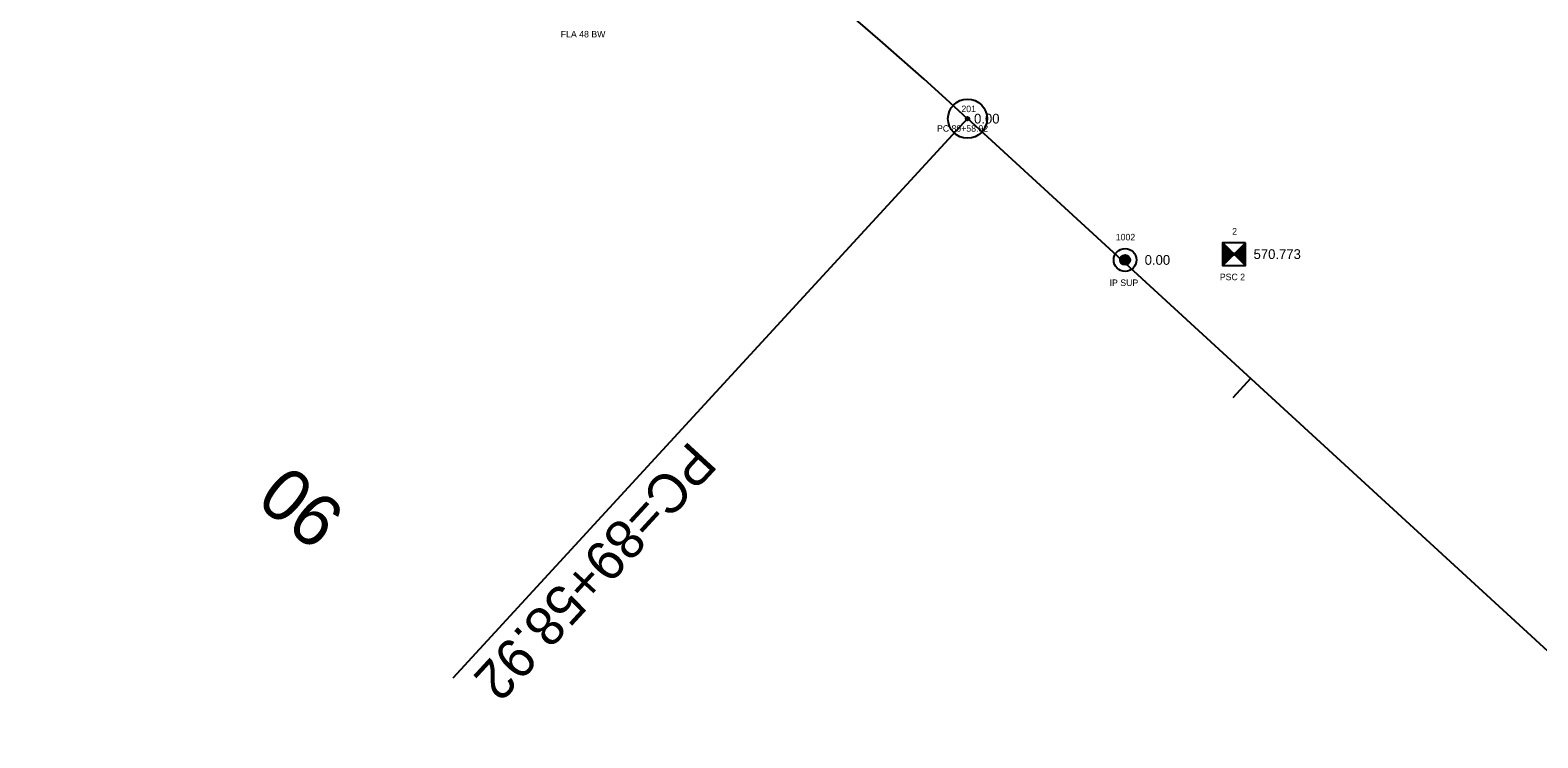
# Model space of a CAD drawing. Extents: x 1529475 to 1532053, y 876698 to 877911.
# Drawn here: x 1531499.1 to 1531730.2, y 876997.3 to 877105.9 of the extents above; entities that cross this region are included whole.
import ezdxf

# ---------------------------------------------------------------- set-up
doc = ezdxf.new("R2010")
doc.units = 0
for name, color, linetype in [('RD_EX_DV_Prop_txCode', 7, 'Continuous'), ('RD_EX_DV_PropPin', 7, 'Continuous'), ('RD_EX_Fence_Other_txCode', 7, 'Continuous'), ('RD_EX_TX_DV_Prop_ELEV', 7, 'Continuous'), ('RD_HC_Cl', 7, 'Continuous'), ('RD_HC_Data', 7, 'Continuous'), ('RD_HC_Data_Tic', 7, 'Continuous'), ('RD_HC_Survey', 7, 'Continuous'), ('RD_HC_Survey_ELEV', 7, 'Continuous'), ('RD_HC_TX_Sta50', 7, 'Continuous'), ('RD_HC_txCode', 7, 'Continuous'), ('RD_SMD_Locator', 7, 'Continuous')]:
    doc.layers.add(name, color=color, linetype=linetype)

msp = doc.modelspace()

# ---------------------------------------------------------------- linework, layer by layer
at = {"layer": 'RD_EX_DV_PropPin'}
for p, q in [((1531666.3, 877070.22), (1531666.3, 877071.07)), ((1531666.33, 877070.17), (1531666.33, 877071.12)), ((1531666.37, 877070.13), (1531666.37, 877071.16)), ((1531666.4, 877070.1), (1531666.4, 877071.2)), ((1531666.44, 877070.06), (1531666.44, 877071.23)), ((1531666.47, 877070.04), (1531666.47, 877071.26)), ((1531666.51, 877070.01), (1531666.51, 877071.28)), ((1531666.54, 877069.99), (1531666.54, 877071.3)), ((1531666.58, 877069.97), (1531666.58, 877071.32)), ((1531666.61, 877069.95), (1531666.61, 877071.34)), ((1531666.65, 877069.94), (1531666.65, 877071.35)), ((1531666.68, 877069.93), (1531666.68, 877071.37)), ((1531666.72, 877069.91), (1531666.72, 877071.38)), ((1531666.75, 877069.91), (1531666.75, 877071.39)), ((1531666.79, 877069.9), (1531666.79, 877071.39)), ((1531666.82, 877069.89), (1531666.82, 877071.4)), ((1531666.86, 877069.89), (1531666.86, 877071.4)), ((1531666.89, 877069.89), (1531666.89, 877071.41)), ((1531666.93, 877069.89), (1531666.93, 877071.41)), ((1531666.96, 877069.89), (1531666.96, 877071.41)), ((1531667, 877069.89), (1531667, 877071.4)), ((1531667.03, 877069.89), (1531667.03, 877071.4)), ((1531667.07, 877069.9), (1531667.07, 877071.39)), ((1531667.1, 877069.91), (1531667.1, 877071.39)), ((1531667.14, 877069.91), (1531667.14, 877071.38)), ((1531667.17, 877069.93), (1531667.17, 877071.37)), ((1531667.21, 877069.94), (1531667.21, 877071.35)), ((1531667.24, 877069.95), (1531667.24, 877071.34)), ((1531667.28, 877069.97), (1531667.28, 877071.32)), ((1531667.31, 877069.99), (1531667.31, 877071.3)), ((1531667.35, 877070.01), (1531667.35, 877071.28)), ((1531667.38, 877070.04), (1531667.38, 877071.26)), ((1531667.42, 877070.06), (1531667.42, 877071.23)), ((1531667.45, 877070.1), (1531667.45, 877071.2)), ((1531667.49, 877070.13), (1531667.49, 877071.16)), ((1531667.52, 877070.17), (1531667.52, 877071.12)), ((1531667.56, 877070.22), (1531667.56, 877071.07)), ((1531666.19, 877070.45), (1531666.19, 877070.84)), ((1531666.23, 877070.35), (1531666.23, 877070.94)), ((1531666.26, 877070.28), (1531666.26, 877071.02)), ((1531667.59, 877070.28), (1531667.59, 877071.02)), ((1531667.63, 877070.35), (1531667.63, 877070.94)), ((1531667.66, 877070.45), (1531667.66, 877070.84))]:
    msp.add_line(p, q, dxfattribs=at)
for radius in [1.75, 0.761]:
    msp.add_circle((1531666.93, 877070.65), radius, dxfattribs=at)
at = {"layer": 'RD_HC_Cl'}
msp.add_line((1531961.27, 876799.7), (1531642.78, 877092.32), dxfattribs=at)
msp.add_arc((1531152.26, 876558.44), 725, 47.4237, 92.33207, dxfattribs=at)
at = {"layer": 'RD_HC_Data'}
msp.add_line((1531642.78, 877092.32), (1531563.91, 877006.48), dxfattribs=at)
for radius in [3, 0.282]:
    msp.add_circle((1531642.78, 877092.32), radius, dxfattribs=at)
at = {"layer": 'RD_HC_Data_Tic'}
msp.add_line((1531686.17, 877052.45), (1531683.46, 877049.51), dxfattribs=at)
at = {"layer": 'RD_HC_Survey'}
for p, q in [((1531681.87, 877073.28), (1531685.37, 877069.79)), ((1531685.37, 877073.28), (1531681.87, 877069.79)), ((1531681.89, 877073.26), (1531681.89, 877069.81)), ((1531681.92, 877073.24), (1531681.92, 877069.83)), ((1531681.94, 877073.21), (1531681.94, 877069.86)), ((1531681.97, 877073.19), (1531681.97, 877069.88)), ((1531681.99, 877073.16), (1531681.99, 877069.91)), ((1531682.02, 877073.14), (1531682.02, 877069.93)), ((1531682.04, 877073.11), (1531682.04, 877069.96)), ((1531682.07, 877073.09), (1531682.07, 877069.98)), ((1531682.09, 877073.06), (1531682.09, 877070.01)), ((1531682.12, 877073.04), (1531682.12, 877070.03)), ((1531682.14, 877073.01), (1531682.14, 877070.06)), ((1531682.17, 877072.99), (1531682.17, 877070.08)), ((1531682.19, 877072.96), (1531682.19, 877070.11)), ((1531682.22, 877072.94), (1531682.22, 877070.13)), ((1531682.24, 877072.91), (1531682.24, 877070.16)), ((1531682.27, 877072.89), (1531682.27, 877070.18)), ((1531682.29, 877072.86), (1531682.29, 877070.21)), ((1531682.32, 877072.84), (1531682.32, 877070.23)), ((1531682.34, 877072.81), (1531682.34, 877070.26)), ((1531682.36, 877072.79), (1531682.36, 877070.28)), ((1531682.39, 877072.77), (1531682.39, 877070.3)), ((1531682.41, 877072.74), (1531682.41, 877070.33)), ((1531682.44, 877072.72), (1531682.44, 877070.35)), ((1531682.46, 877072.69), (1531682.46, 877070.38)), ((1531682.49, 877072.67), (1531682.49, 877070.4)), ((1531682.51, 877072.64), (1531682.51, 877070.43)), ((1531682.54, 877072.62), (1531682.54, 877070.45)), ((1531682.56, 877072.59), (1531682.56, 877070.48)), ((1531682.59, 877072.57), (1531682.59, 877070.5)), ((1531682.61, 877072.54), (1531682.61, 877070.53)), ((1531682.64, 877072.52), (1531682.64, 877070.55)), ((1531682.66, 877072.49), (1531682.66, 877070.58)), ((1531682.69, 877072.47), (1531682.69, 877070.6)), ((1531682.71, 877072.44), (1531682.71, 877070.63)), ((1531682.74, 877072.42), (1531682.74, 877070.65)), ((1531682.76, 877072.39), (1531682.76, 877070.68)), ((1531682.79, 877072.37), (1531682.79, 877070.7)), ((1531682.81, 877072.34), (1531682.81, 877070.73)), ((1531682.83, 877072.32), (1531682.83, 877070.75)), ((1531682.86, 877072.3), (1531682.86, 877070.77)), ((1531682.88, 877072.27), (1531682.88, 877070.8)), ((1531682.91, 877072.25), (1531682.91, 877070.82)), ((1531682.93, 877072.22), (1531682.93, 877070.85)), ((1531682.96, 877072.2), (1531682.96, 877070.87)), ((1531682.98, 877072.17), (1531682.98, 877070.9)), ((1531683.01, 877072.15), (1531683.01, 877070.92)), ((1531683.03, 877072.12), (1531683.03, 877070.95)), ((1531683.06, 877072.1), (1531683.06, 877070.97)), ((1531683.08, 877072.07), (1531683.08, 877071)), ((1531683.11, 877072.05), (1531683.11, 877071.02)), ((1531683.13, 877072.02), (1531683.13, 877071.05)), ((1531683.16, 877072), (1531683.16, 877071.07)), ((1531683.18, 877071.97), (1531683.18, 877071.1)), ((1531683.21, 877071.95), (1531683.21, 877071.12)), ((1531683.23, 877071.92), (1531683.23, 877071.15)), ((1531683.26, 877071.9), (1531683.26, 877071.17)), ((1531683.28, 877071.87), (1531683.28, 877071.2)), ((1531683.31, 877071.85), (1531683.31, 877071.22)), ((1531683.33, 877071.82), (1531683.33, 877071.25)), ((1531683.35, 877071.8), (1531683.35, 877071.27)), ((1531683.38, 877071.78), (1531683.38, 877071.29)), ((1531683.4, 877071.75), (1531683.4, 877071.32)), ((1531683.43, 877071.73), (1531683.43, 877071.34)), ((1531683.45, 877071.7), (1531683.45, 877071.37)), ((1531683.48, 877071.68), (1531683.48, 877071.39)), ((1531683.5, 877071.65), (1531683.5, 877071.42)), ((1531683.53, 877071.63), (1531683.53, 877071.44)), ((1531683.55, 877071.6), (1531683.55, 877071.47)), ((1531683.58, 877071.58), (1531683.58, 877071.49)), ((1531683.6, 877071.55), (1531683.6, 877071.52)), ((1531683.64, 877071.55), (1531683.64, 877071.52)), ((1531683.66, 877071.58), (1531683.66, 877071.49)), ((1531683.69, 877071.6), (1531683.69, 877071.47)), ((1531683.71, 877071.63), (1531683.71, 877071.44)), ((1531683.74, 877071.65), (1531683.74, 877071.42)), ((1531683.76, 877071.68), (1531683.76, 877071.39)), ((1531683.79, 877071.7), (1531683.79, 877071.37)), ((1531683.81, 877071.73), (1531683.81, 877071.34)), ((1531683.84, 877071.75), (1531683.84, 877071.32)), ((1531683.86, 877071.78), (1531683.86, 877071.29)), ((1531683.88, 877071.8), (1531683.88, 877071.27)), ((1531683.91, 877071.82), (1531683.91, 877071.25)), ((1531683.93, 877071.85), (1531683.93, 877071.22)), ((1531683.96, 877071.87), (1531683.96, 877071.2)), ((1531683.98, 877071.9), (1531683.98, 877071.17)), ((1531684.01, 877071.92), (1531684.01, 877071.15)), ((1531684.03, 877071.95), (1531684.03, 877071.12)), ((1531684.06, 877071.97), (1531684.06, 877071.1)), ((1531684.08, 877072), (1531684.08, 877071.07)), ((1531684.11, 877072.02), (1531684.11, 877071.05)), ((1531684.13, 877072.05), (1531684.13, 877071.02)), ((1531684.16, 877072.07), (1531684.16, 877071)), ((1531684.18, 877072.1), (1531684.18, 877070.97)), ((1531684.21, 877072.12), (1531684.21, 877070.95)), ((1531684.23, 877072.15), (1531684.23, 877070.92)), ((1531684.26, 877072.17), (1531684.26, 877070.9)), ((1531684.28, 877072.2), (1531684.28, 877070.87)), ((1531684.31, 877072.22), (1531684.31, 877070.85)), ((1531684.33, 877072.25), (1531684.33, 877070.82)), ((1531684.35, 877072.27), (1531684.35, 877070.8)), ((1531684.38, 877072.3), (1531684.38, 877070.77)), ((1531684.4, 877072.32), (1531684.4, 877070.75)), ((1531684.43, 877072.34), (1531684.43, 877070.73)), ((1531684.45, 877072.37), (1531684.45, 877070.7)), ((1531684.48, 877072.39), (1531684.48, 877070.68)), ((1531684.5, 877072.42), (1531684.5, 877070.65)), ((1531684.53, 877072.44), (1531684.53, 877070.63)), ((1531684.55, 877072.47), (1531684.55, 877070.6)), ((1531684.58, 877072.49), (1531684.58, 877070.58)), ((1531684.6, 877072.52), (1531684.6, 877070.55)), ((1531684.63, 877072.54), (1531684.63, 877070.53)), ((1531684.65, 877072.57), (1531684.65, 877070.5)), ((1531684.68, 877072.59), (1531684.68, 877070.48)), ((1531684.7, 877072.62), (1531684.7, 877070.45)), ((1531684.73, 877072.64), (1531684.73, 877070.43)), ((1531684.75, 877072.67), (1531684.75, 877070.4)), ((1531684.78, 877072.69), (1531684.78, 877070.38)), ((1531684.8, 877072.72), (1531684.8, 877070.35)), ((1531684.83, 877072.74), (1531684.83, 877070.33)), ((1531684.85, 877072.77), (1531684.85, 877070.3)), ((1531684.87, 877072.79), (1531684.87, 877070.28)), ((1531684.9, 877072.81), (1531684.9, 877070.26)), ((1531684.92, 877072.84), (1531684.92, 877070.23)), ((1531684.95, 877072.86), (1531684.95, 877070.21)), ((1531684.97, 877072.89), (1531684.97, 877070.18)), ((1531685, 877072.91), (1531685, 877070.16)), ((1531685.02, 877072.94), (1531685.02, 877070.13)), ((1531685.05, 877072.96), (1531685.05, 877070.11)), ((1531685.07, 877072.99), (1531685.07, 877070.08)), ((1531685.1, 877073.01), (1531685.1, 877070.06)), ((1531685.12, 877073.04), (1531685.12, 877070.03)), ((1531685.15, 877073.06), (1531685.15, 877070.01)), ((1531685.17, 877073.09), (1531685.17, 877069.98)), ((1531685.2, 877073.11), (1531685.2, 877069.96)), ((1531685.22, 877073.14), (1531685.22, 877069.93)), ((1531685.25, 877073.16), (1531685.25, 877069.91)), ((1531685.27, 877073.19), (1531685.27, 877069.88)), ((1531685.3, 877073.21), (1531685.3, 877069.86)), ((1531685.32, 877073.24), (1531685.32, 877069.83)), ((1531685.34, 877073.26), (1531685.34, 877069.81))]:
    msp.add_line(p, q, dxfattribs=at)
msp.add_lwpolyline([(1531685.37, 877073.28), (1531681.87, 877073.28), (1531681.87, 877069.79), (1531685.37, 877069.79)], close=True, dxfattribs=at)
at = {"layer": 'RD_SMD_Locator'}
for centre in [(1531642.78, 877092.32), (1531683.62, 877071.54), (1531666.93, 877070.65)]:
    msp.add_circle(centre, 0.15, dxfattribs=at)

# ---------------------------------------------------------------- texts
at = {"layer": 'RD_EX_DV_Prop_txCode'}
for s, p in [('1002', (1531665.5, 877073.65)), ('IP SUP', (1531664.56, 877066.65))]:
    msp.add_text(s, height=1, dxfattribs=at).set_placement(p)
at = {"layer": 'RD_EX_Fence_Other_txCode'}
msp.add_text('FLA 48 BW', height=1, dxfattribs=at).set_placement((1531580.44, 877104.78))
at = {"layer": 'RD_EX_TX_DV_Prop_ELEV'}
msp.add_text('0.00', height=1.5, dxfattribs=at).set_placement((1531669.93, 877069.9))
at = {"layer": 'RD_HC_Data'}
msp.add_text('PC=89+58.92', height=6, rotation=227.4237, dxfattribs=at).set_placement((1531600.27, 877043.1))
at = {"layer": 'RD_HC_Survey_ELEV'}
for s, p in [('0.00', (1531643.78, 877091.57)), ('570.773', (1531686.62, 877070.79))]:
    msp.add_text(s, height=1.5, dxfattribs=at).set_placement(p)
at = {"layer": 'RD_HC_TX_Sta50'}
msp.add_text('90', height=8, rotation=140.6698, dxfattribs=at).set_placement((1531547.8, 877032.02))
at = {"layer": 'RD_HC_txCode'}
for s, p in [('201', (1531641.84, 877093.32)), ('PC 89+58.92', (1531638.1, 877090.32)), ('2', (1531683.34, 877074.54)), ('PSC 2', (1531681.45, 877067.54))]:
    msp.add_text(s, height=1, dxfattribs=at).set_placement(p)

doc.saveas('drawing.dxf')
